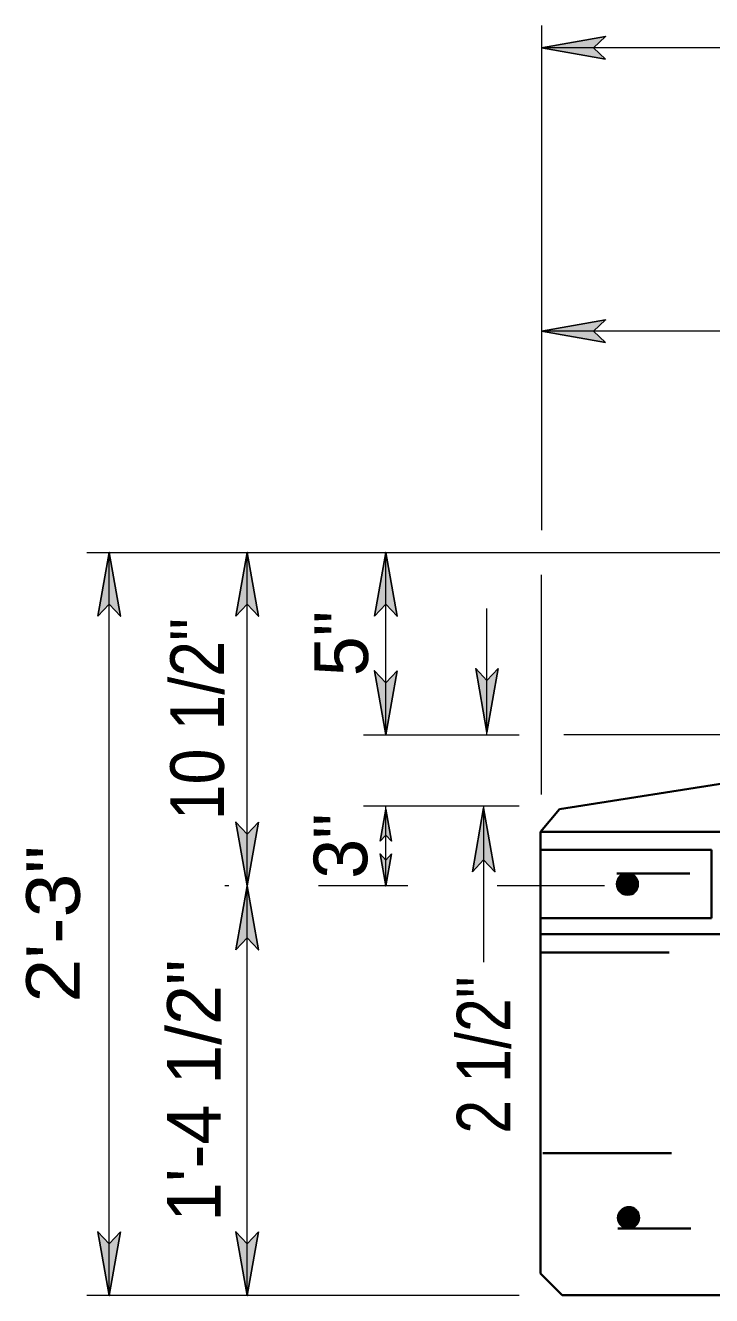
# Model space of a CAD drawing. Extents: x 12.6 to 19.5, y 6.1 to 16.3.
# Drawn here: x 14.875 to 15.643, y 14.364 to 15.785 of the extents above; entities that cross this region are included whole.
import ezdxf
from ezdxf.enums import TextEntityAlignment as Align

# ---------------------------------------------------------------- set-up
doc = ezdxf.new("R2010")
doc.units = 0
doc.header["$LTSCALE"] = 0.024
doc.linetypes.add('DOT_DASHED', pattern=[7.7, 5, -1.2, 0.3, -1.2])
doc.linetypes.add('LONG_DASHED', pattern=[7.5, 6, -1.5])
for name, color, linetype, lineweight in [('1', 7, 'Continuous', 35), ('10', 7, 'Continuous', 25), ('12', 7, 'Continuous', 53)]:
    doc.layers.add(name, color=color, linetype=linetype, lineweight=lineweight)

msp = doc.modelspace()

# ---------------------------------------------------------------- hatches: boundary and pattern name
at = {"layer": '10'}
for points in [[(15.5239, 15.7478), (15.4524, 15.7604), (15.5239, 15.773), (15.5104, 15.7604)], [(15.5239, 15.4307), (15.4524, 15.4433), (15.5239, 15.4559), (15.5104, 15.4433)], [(14.956, 15.1242), (14.9686, 15.1957), (14.9812, 15.1242), (14.9686, 15.1377)], [(15.1104, 15.1242), (15.123, 15.1957), (15.1356, 15.1242), (15.123, 15.1377)], [(15.2654, 15.1242), (15.278, 15.1957), (15.2906, 15.1242), (15.278, 15.1377)], [(15.2906, 15.0632), (15.278, 14.9917), (15.2654, 15.0632), (15.278, 15.0497)], [(15.4039, 15.0657), (15.3913, 14.9942), (15.3787, 15.0657), (15.3913, 15.0522)], [(15.2717, 14.8726), (15.278, 14.9083), (15.2843, 14.8726), (15.278, 14.8793)], [(15.3749, 14.8383), (15.3875, 14.9098), (15.4001, 14.8383), (15.3875, 14.8518)], [(15.1356, 14.8939), (15.123, 14.8224), (15.1104, 14.8939), (15.123, 14.8804)], [(15.2843, 14.8582), (15.278, 14.8224), (15.2717, 14.8582), (15.278, 14.8514)], [(15.1104, 14.7509), (15.123, 14.8224), (15.1356, 14.7509), (15.123, 14.7644)], [(14.9812, 14.4355), (14.9686, 14.364), (14.956, 14.4355), (14.9686, 14.422)], [(15.1356, 14.4355), (15.123, 14.364), (15.1104, 14.4355), (15.123, 14.422)]]:
    msp.add_hatch(color=256, dxfattribs=at).paths.add_polyline_path(points)

# ---------------------------------------------------------------- linework, layer by layer
at = {"layer": '1'}
for p, q in [((16.0011, 14.9917), (15.4725, 14.9083)), ((15.4725, 14.9083), (15.451, 14.8831)), ((15.451, 14.8831), (16.3776, 14.8831)), ((15.451, 14.8628), (15.6426, 14.8628)), ((15.6426, 14.7865), (15.6426, 14.8628)), ((15.5364, 14.8364), (15.6181, 14.8364)), ((15.451, 14.7865), (15.6426, 14.7865)), ((15.4524, 14.7686), (16.379, 14.7686)), ((15.5376, 14.439), (15.6193, 14.439)), ((15.451, 14.3888), (15.4755, 14.3643)), ((16.3776, 14.3643), (15.4755, 14.3643))]:
    msp.add_line(p, q, dxfattribs=at)
at = {"layer": '1', "linetype": 'LONG_DASHED'}
for p, q in [((15.451, 14.7481), (16.3747, 14.7481)), ((15.4537, 14.5235), (16.3774, 14.5235))]:
    msp.add_line(p, q, dxfattribs=at)
at = {"layer": '1'}
msp.add_lwpolyline([(15.451, 14.3888), (15.451, 14.4995), (15.451, 14.8469), (15.451, 14.8831)], dxfattribs=at)
for centre, radius in [((15.5484, 14.82446), 0.0118), ((15.54841, 14.82476), 0.01119), ((15.54867, 14.82442), 0.01108), ((15.54873, 14.8241), 0.01088), ((15.549, 14.82346), 0.01098), ((15.5487, 14.82432), 0.01039), ((15.5489, 14.82415), 0.0102), ((15.54904, 14.8242), 0.00983), ((15.54917, 14.82391), 0.00973), ((15.54929, 14.82368), 0.0096), ((15.54944, 14.82337), 0.00955), ((15.54958, 14.82315), 0.00942), ((15.54927, 14.82351), 0.00878), ((15.54954, 14.82327), 0.00864), ((15.55007, 14.82364), 0.00846), ((15.55012, 14.82363), 0.00813), ((15.54995, 14.82364), 0.00759), ((15.55022, 14.82349), 0.00732), ((15.55034, 14.82349), 0.00717), ((15.55047, 14.82353), 0.00694), ((15.55027, 14.82331), 0.00626), ((15.55061, 14.82341), 0.00646), ((15.55025, 14.82315), 0.00587), ((15.5504, 14.82309), 0.0055), ((15.55049, 14.82307), 0.00503), ((15.55052, 14.82307), 0.00469), ((15.55056, 14.82288), 0.00456), ((15.55083, 14.82299), 0.00466), ((15.55074, 14.82293), 0.0042), ((15.55081, 14.82285), 0.0039), ((15.55083, 14.82277), 0.00365), ((15.55076, 14.82288), 0.00348), ((15.55079, 14.82272), 0.00314), ((15.55084, 14.82277), 0.00286), ((15.55111, 14.82268), 0.00275), ((15.55105, 14.82282), 0.00252), ((15.55084, 14.82272), 0.00208), ((15.55093, 14.82266), 0.00199), ((15.55059, 14.82261), 0.00142), ((15.55137, 14.8226), 0.00219), ((15.55096, 14.82263), 0.00155), ((15.55067, 14.82261), 0.000996), ((15.55111, 14.8226), 0.00127), ((15.55074, 14.82263), 0.000827), ((15.55089, 14.82253), 0.000776), ((15.55091, 14.82265), 0.000456), ((15.5496, 14.45104), 0.0118), ((15.54961, 14.45075), 0.01119), ((15.54987, 14.45109), 0.01108), ((15.54993, 14.45141), 0.01088), ((15.5502, 14.45205), 0.01098), ((15.5499, 14.45119), 0.01039), ((15.5501, 14.45136), 0.0102), ((15.55024, 14.45131), 0.00983), ((15.55037, 14.45159), 0.00973), ((15.55049, 14.45183), 0.0096), ((15.55064, 14.45213), 0.00955), ((15.55078, 14.45235), 0.00942), ((15.55047, 14.452), 0.00878), ((15.55074, 14.45224), 0.00864), ((15.55127, 14.45186), 0.00846), ((15.55132, 14.45188), 0.00813), ((15.55115, 14.45186), 0.00759), ((15.55142, 14.45202), 0.00732), ((15.55154, 14.45202), 0.00717), ((15.55167, 14.45198), 0.00694), ((15.55147, 14.4522), 0.00626), ((15.55181, 14.4521), 0.00646), ((15.55145, 14.45235), 0.00587), ((15.5516, 14.45242), 0.0055), ((15.55169, 14.45244), 0.00503), ((15.55172, 14.45244), 0.00469), ((15.55176, 14.45262), 0.00456), ((15.55203, 14.45252), 0.00466), ((15.55194, 14.45257), 0.0042), ((15.55201, 14.45266), 0.0039), ((15.55203, 14.45274), 0.00365), ((15.55196, 14.45262), 0.00348), ((15.55199, 14.45279), 0.00314), ((15.55204, 14.45274), 0.00286), ((15.55231, 14.45283), 0.00275), ((15.55225, 14.45269), 0.00252), ((15.55204, 14.45279), 0.00208), ((15.55213, 14.45284), 0.00199), ((15.55179, 14.45289), 0.00142), ((15.55257, 14.45291), 0.00219), ((15.55216, 14.45288), 0.00155), ((15.55187, 14.45289), 0.000996), ((15.55231, 14.45291), 0.00127), ((15.55194, 14.45288), 0.000827), ((15.55209, 14.45298), 0.000776), ((15.55211, 14.45286), 0.000456)]:
    msp.add_circle(centre, radius, dxfattribs=at)
at = {"layer": '10', "lineweight": 13}
for p, q in [((15.4524, 15.7854), (15.4524, 15.2207)), ((16.3771, 15.7604), (15.4524, 15.7604)), ((14.9436, 15.1957), (15.9761, 15.1957)), ((14.9686, 14.364), (14.9686, 15.1957)), ((15.278, 14.9917), (15.278, 15.1957)), ((15.4524, 14.9248), (15.4524, 15.1707)), ((15.3913, 14.9917), (15.3913, 15.1329)), ((15.253, 14.9917), (15.4274, 14.9917)), ((15.7979, 14.9917), (15.4774, 14.9917)), ((15.4274, 14.9116), (15.253, 14.9116)), ((15.278, 14.8224), (15.278, 14.9116)), ((15.3875, 14.9116), (15.3875, 14.7372)), ((15.4274, 14.364), (14.9436, 14.364))]:
    msp.add_line(p, q, dxfattribs=at)
at = {"layer": '10'}
for p, q in [((15.4524, 15.7604), (15.5239, 15.773)), ((15.4524, 15.7604), (15.5239, 15.7478)), ((15.4524, 15.4433), (15.5239, 15.4559)), ((15.4524, 15.4433), (15.5239, 15.4307)), ((14.9686, 15.1957), (14.956, 15.1242)), ((14.9686, 15.1957), (14.9812, 15.1242)), ((15.123, 15.1957), (15.1104, 15.1242)), ((15.123, 15.1957), (15.1356, 15.1242)), ((15.278, 15.1957), (15.2654, 15.1242)), ((15.278, 15.1957), (15.2906, 15.1242)), ((15.278, 14.9917), (15.2654, 15.0632)), ((15.278, 14.9917), (15.2906, 15.0632)), ((15.3913, 14.9942), (15.3787, 15.0657)), ((15.3913, 14.9942), (15.4039, 15.0657)), ((15.278, 14.9083), (15.2717, 14.8726)), ((15.278, 14.9083), (15.2843, 14.8726)), ((15.3875, 14.9098), (15.3749, 14.8383)), ((15.3875, 14.9098), (15.4001, 14.8383)), ((15.123, 14.8224), (15.1104, 14.8939)), ((15.123, 14.8224), (15.1356, 14.8939)), ((15.278, 14.8224), (15.2717, 14.8582)), ((15.278, 14.8224), (15.2843, 14.8582)), ((15.123, 14.8224), (15.1104, 14.7509)), ((15.123, 14.8224), (15.1356, 14.7509)), ((14.9686, 14.364), (14.956, 14.4355)), ((14.9686, 14.364), (14.9812, 14.4355)), ((15.123, 14.364), (15.1104, 14.4355)), ((15.123, 14.364), (15.1356, 14.4355))]:
    msp.add_line(p, q, dxfattribs=at)
at = {"layer": '10', "linetype": 'DOT_DASHED', "lineweight": 13}
msp.add_line((15.5226, 14.8224), (15.098, 14.8224), dxfattribs=at)
at = {"layer": '10'}
for points in [[(15.5239, 15.7478), (15.4524, 15.7604), (15.5239, 15.773), (15.5104, 15.7604)], [(15.5239, 15.4307), (15.4524, 15.4433), (15.5239, 15.4559), (15.5104, 15.4433)], [(14.956, 15.1242), (14.9686, 15.1957), (14.9812, 15.1242), (14.9686, 15.1377)], [(15.1104, 15.1242), (15.123, 15.1957), (15.1356, 15.1242), (15.123, 15.1377)], [(15.2654, 15.1242), (15.278, 15.1957), (15.2906, 15.1242), (15.278, 15.1377)], [(15.2906, 15.0632), (15.278, 14.9917), (15.2654, 15.0632), (15.278, 15.0497)], [(15.4039, 15.0657), (15.3913, 14.9942), (15.3787, 15.0657), (15.3913, 15.0522)], [(15.2717, 14.8726), (15.278, 14.9083), (15.2843, 14.8726), (15.278, 14.8793)], [(15.3749, 14.8383), (15.3875, 14.9098), (15.4001, 14.8383), (15.3875, 14.8518)], [(15.1356, 14.8939), (15.123, 14.8224), (15.1104, 14.8939), (15.123, 14.8804)], [(15.2843, 14.8582), (15.278, 14.8224), (15.2717, 14.8582), (15.278, 14.8514)], [(15.1104, 14.7509), (15.123, 14.8224), (15.1356, 14.7509), (15.123, 14.7644)], [(14.9812, 14.4355), (14.9686, 14.364), (14.956, 14.4355), (14.9686, 14.422)], [(15.1356, 14.4355), (15.123, 14.364), (15.1104, 14.4355), (15.123, 14.422)]]:
    msp.add_lwpolyline(points, close=True, dxfattribs=at)
for points in [[(15.5239, 15.7478), (15.5104, 15.7604), (15.5239, 15.773)], [(15.5239, 15.4307), (15.5104, 15.4433), (15.5239, 15.4559)], [(14.956, 15.1242), (14.9686, 15.1377), (14.9812, 15.1242)], [(15.1104, 15.1242), (15.123, 15.1377), (15.1356, 15.1242)], [(15.2654, 15.1242), (15.278, 15.1377), (15.2906, 15.1242)], [(15.2906, 15.0632), (15.278, 15.0497), (15.2654, 15.0632)], [(15.4039, 15.0657), (15.3913, 15.0522), (15.3787, 15.0657)], [(15.1356, 14.8939), (15.123, 14.8804), (15.1104, 14.8939)], [(15.2717, 14.8726), (15.278, 14.8793), (15.2843, 14.8726)], [(15.2843, 14.8582), (15.278, 14.8514), (15.2717, 14.8582)], [(15.3749, 14.8383), (15.3875, 14.8518), (15.4001, 14.8383)], [(15.1104, 14.7509), (15.123, 14.7644), (15.1356, 14.7509)], [(14.9812, 14.4355), (14.9686, 14.422), (14.956, 14.4355)], [(15.1356, 14.4355), (15.123, 14.422), (15.1104, 14.4355)]]:
    msp.add_lwpolyline(points, dxfattribs=at)
at = {"layer": '10', "lineweight": 13}
for points in [[(16.2907, 15.4433), (16.0011, 15.4433), (15.4524, 15.4433)], [(15.123, 14.364), (15.123, 14.8224), (15.123, 15.1957)]]:
    msp.add_lwpolyline(points, dxfattribs=at)

# ---------------------------------------------------------------- texts
at = {"layer": '12'}
for s, p in [('5"', (15.2582, 15.0937)), ('3"', (15.2573, 14.86705)), ('1\'-4 1/2"', (15.0934, 14.5932))]:
    msp.add_text(s, height=0.06, rotation=90, dxfattribs=at).set_placement(p, align=Align.CENTER)
for s, width, p in [('10 1/2"', 0.9, (15.0969, 15.00905)), ('2\'-3"', 1.1, (14.9357, 14.77975))]:
    msp.add_text(s, height=0.06, rotation=90, dxfattribs=dict(at, width=width)).set_placement(p, align=Align.CENTER)
at = {"layer": '12', "width": 0.85}
msp.add_text('2 1/2"', height=0.06, rotation=90, dxfattribs=at).set_placement((15.4175, 14.7211), align=Align.RIGHT)

doc.saveas('drawing.dxf')
